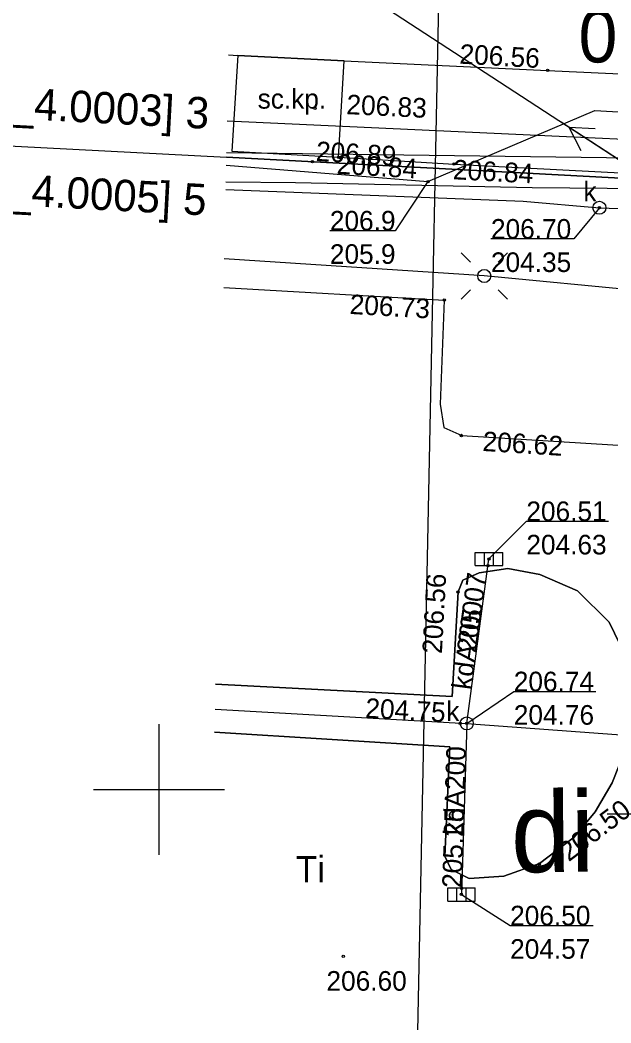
# Model space of a CAD drawing. Extents: x 6512606 to 6513006, y 6022524 to 6022728.
# Drawn here: x 6512694.69 to 6512717.27, y 6022641.08 to 6022679.43 of the extents above; entities that cross this region are included whole.
import ezdxf

# ---------------------------------------------------------------- set-up
doc = ezdxf.new("R2010")
doc.units = 0
for name, color, linetype in [('20', 7, 'Continuous'), ('208-opis obrębu', 7, 'Continuous'), ('210-oznaczenie konturu użytku gruntowego', 7, 'Continuous'), ('216-obręb ewidencyjny', 7, 'Continuous'), ('218-kontur użytku gruntowego', 7, 'Continuous'), ('219-działka ewidencyjna', 7, 'Continuous'), ('4', 7, 'Continuous'), ('chodnik (powierzchnia)', 7, 'Continuous'), ('Default', 7, 'Continuous'), ('jezdnia (powierzchnia)', 7, 'Continuous'), ('kratka ściekowa (punkt)', 7, 'Continuous'), ('krawężnik (linia)', 7, 'Continuous'), ('latarnia (punkt)', 7, 'Continuous'), ('maxp_inst_wodociągowa', 7, 'Continuous'), ('Obszar opracowania', 7, 'Continuous'), ('plac (powierzchnia)', 7, 'Continuous'), ('przewód elektroenergetyczny (linia)', 7, 'Continuous'), ('przewód elektroenergetyczny niskiego napięcia (linia)', 7, 'Continuous'), ('przewód elektroenergetyczny niskiego napięcia (linia) - symbol', 7, 'Continuous'), ('przewód kanalizacyjny (linia)', 7, 'Continuous'), ('przewód kanalizacyjny (linia)-Atr1', 7, 'Continuous'), ('przewód wodociągowy (linia)', 7, 'Continuous'), ('psr_os', 7, 'Continuous'), ('punkt o określonej wysokości (sieć elektroenergetyczna)', 7, 'Continuous'), ('punkt o określonej wysokości (sieć elektroenergetyczna)-Atr2', 7, 'Continuous'), ('punkt o określonej wysokości (sieć elektroenergetyczna)-Atr3', 7, 'Continuous'), ('punkt o określonej wysokości (sieć kanalizacyjna)', 7, 'Continuous'), ('punkt o określonej wysokości (sieć kanalizacyjna)-Atr2', 7, 'Continuous'), ('punkt o określonej wysokości (sieć kanalizacyjna)-Atr3', 7, 'Continuous'), ('punkt wysokościowy sztuczny', 7, 'Continuous'), ('punkt wysokościowy sztuczny-Atr2', 7, 'Continuous'), ('właz okrągły - siec kanalizacyjna (punkt)', 7, 'Continuous'), ('właz okrągły - siec kanalizacyjna (punkt)-Atr17', 7, 'Continuous'), ('ścieżka (powierzchnia)', 7, 'Continuous'), ('ścieżka (powierzchnia)-Atr17', 7, 'Continuous')]:
    doc.layers.add(name, color=color, linetype=linetype)

# ---------------------------------------------------------------- blocks, each defined once
blk = doc.blocks.new('PE04')
at = {"layer": 'Default'}
for p, q in [((46.5, 0), (37.84, 5)), ((6.5, 0), (0, 0)), ((6.5, 0), (16.5, 0)), ((16.5, 0), (26.5, 0)), ((26.5, 0), (36.5, 0)), ((36.5, 0), (46.5, 0)), ((46.5, 0), (37.84, -5)), ((46.5, 0), (50, 0))]:
    blk.add_line(p, q, dxfattribs=at)
blk = doc.blocks.new('PW01')
at = {"layer": 'Default'}
blk.add_circle((0, 0), 0.45, dxfattribs=at)
blk = doc.blocks.new('PW02')
at = {"layer": 'Default'}
blk.add_circle((0, 0), 0.45, dxfattribs=at)
blk = doc.blocks.new('US05')
at = {"layer": 'Default'}
for p, q in [((-5.25, -2.5), (-5.25, 2.5)), ((-5.25, 2.5), (-1.75, 2.5)), ((-1.75, -2.5), (-1.75, 2.5)), ((-1.75, 2.5), (1.75, 2.5)), ((1.75, -2.5), (1.75, 2.5)), ((1.75, 2.5), (5.25, 2.5)), ((5.25, -2.5), (5.25, 2.5)), ((-5.25, -2.5), (-1.75, -2.5)), ((-1.75, -2.5), (1.75, -2.5)), ((1.75, -2.5), (5.25, -2.5))]:
    blk.add_line(p, q, dxfattribs=at)
blk = doc.blocks.new('US22')
at = {"layer": 'Default'}
blk.add_circle((0, 0), 2.5, dxfattribs=at)
blk = doc.blocks.new('SM01')
at = {"layer": 'Default'}
for p, q in [((-5.3, 5.31), (-8.83, 8.84)), ((5.31, 5.31), (8.84, 8.84)), ((-5.3, -5.3), (-8.83, -8.83)), ((5.31, -5.3), (8.84, -8.83))]:
    blk.add_line(p, q, dxfattribs=at)
blk.add_circle((0, 0), 2.5, dxfattribs=at)

msp = doc.modelspace()

# ---------------------------------------------------------------- linework, layer by layer
at = {"layer": '20'}
msp.add_line((6512722.691, 6022649.066), (6512717.122, 6022649.066), dxfattribs=at)
at = {"layer": '216-obręb ewidencyjny'}
for points in [[(6512688.62, 6022674.91), (6512702.58, 6022674.18), (6512725.78, 6022672.95), (6512730.35, 6022672.71), (6512735.76, 6022672.94), (6512745.51, 6022673.33), (6512754.87, 6022673.72), (6512768.24, 6022674.27), (6512785.56, 6022674.74), (6512790.49, 6022674.74), (6512796.96, 6022674.74), (6512801.96, 6022670.34), (6512828.67, 6022670.98), (6512833.61, 6022675.02), (6512836.69, 6022675.17), (6512851.94, 6022675.93)], [(6512852.25, 6022608.25), (6512838.47, 6022634.29), (6512825.37, 6022649.66), (6512810.18, 6022663.28), (6512801.96, 6022670.34), (6512796.96, 6022674.74), (6512790.49, 6022674.74), (6512785.56, 6022674.74), (6512768.24, 6022674.27), (6512754.87, 6022673.72), (6512745.51, 6022673.33), (6512735.76, 6022672.94), (6512730.35, 6022672.71), (6512725.78, 6022672.95), (6512702.575, 6022674.177)]]:
    msp.add_lwpolyline(points, dxfattribs=at)
at = {"layer": '218-kontur użytku gruntowego'}
for points in [[(6512725.78, 6022672.95), (6512702.575, 6022674.178)], [(6512702.575, 6022674.178), (6512725.78, 6022672.95)]]:
    msp.add_lwpolyline(points, dxfattribs=at)
at = {"layer": '219-działka ewidencyjna'}
msp.add_lwpolyline([(6512702.575, 6022674.177), (6512725.78, 6022672.95)], dxfattribs=at)
at = {"layer": '4'}
msp.add_lwpolyline([(6512702.575, 6022674.177), (6512725.78, 6022672.95)], dxfattribs=at)
at = {"layer": 'chodnik (powierzchnia)'}
msp.add_lwpolyline([(6512706.86, 6022674.18), (6512711.28, 6022673.92), (6512732.54, 6022672.81)], dxfattribs=at)
at = {"layer": 'Default'}
for p, q in [((6512700, 6022647.5), (6512700, 6022652.5)), ((6512697.5, 6022650), (6512702.5, 6022650))]:
    msp.add_line(p, q, dxfattribs=at)
at = {"layer": 'jezdnia (powierzchnia)'}
msp.add_lwpolyline([(6512707.08, 6022677.87), (6512714.85, 6022677.5), (6512727.62, 6022676.91), (6512733.49, 6022676.74), (6512737.49, 6022676.65), (6512740.34, 6022676.65), (6512746.78, 6022676.72), (6512757.48, 6022676.77)], dxfattribs=at)
at = {"layer": 'krawężnik (linia)'}
for points in [[(6512702.655, 6022678.093), (6512703.01, 6022678.07), (6512707.08, 6022677.87)], [(6512707.08, 6022677.87), (6512714.85, 6022677.5), (6512727.62, 6022676.91), (6512733.49, 6022676.74), (6512737.49, 6022676.65), (6512740.34, 6022676.65), (6512746.78, 6022676.72), (6512757.48, 6022676.77)], [(6512702.473, 6022669.202), (6512710.9, 6022668.72), (6512710.75, 6022664.74), (6512710.88, 6022663.85), (6512711.57, 6022663.54), (6512725.79, 6022662.66), (6512724.94, 6022645.24), (6512724.45, 6022635.71), (6512706.43, 6022636.73), (6512701.814, 6022636.999)], [(6512711.21, 6022653.56), (6512711.43, 6022657.56), (6512711.61, 6022658.01), (6512712.23, 6022658.29), (6512713.33, 6022658.45), (6512714.55, 6022658.23), (6512715.99, 6022657.6), (6512717.2, 6022656.4), (6512718.01, 6022654.75), (6512718.25, 6022653.19), (6512717.88, 6022651.68), (6512717.32, 6022650.26), (6512716.67, 6022649.15), (6512715.87, 6022648.18), (6512714.54, 6022647.17), (6512713.18, 6022646.69), (6512711.85, 6022646.6), (6512711.17, 6022646.95), (6512710.93, 6022647.46), (6512711.12, 6022651.64), (6512702.125, 6022652.199)], [(6512702.163, 6022654.037), (6512711.21, 6022653.56)]]:
    msp.add_lwpolyline(points, dxfattribs=at)
at = {"layer": 'Obszar opracowania'}
msp.add_lwpolyline([(6512710.98, 6022693.84), (6512748.35, 6022694.16), (6512798.11, 6022695.25), (6512807.47, 6022695.46), (6512809.66, 6022606.87), (6512863.71, 6022622.03), (6512875.13, 6022581.36), (6512755.22, 6022535.25), (6512691.61, 6022568.03), (6512709.16, 6022605.16)], close=True, dxfattribs=at)
at = {"layer": 'plac (powierzchnia)'}
for points in [[(6512702.125, 6022652.199), (6512711.12, 6022651.64), (6512710.93, 6022647.46), (6512711.17, 6022646.95), (6512711.85, 6022646.6), (6512713.18, 6022646.69), (6512714.54, 6022647.17), (6512715.87, 6022648.18), (6512716.67, 6022649.15), (6512717.32, 6022650.26), (6512717.88, 6022651.68), (6512718.25, 6022653.19), (6512718.01, 6022654.75), (6512717.2, 6022656.4), (6512715.99, 6022657.6), (6512714.55, 6022658.23), (6512713.33, 6022658.45), (6512712.23, 6022658.29), (6512711.61, 6022658.01), (6512711.43, 6022657.56), (6512711.21, 6022653.56)], [(6512711.21, 6022653.56), (6512702.163, 6022654.037)]]:
    msp.add_lwpolyline(points, dxfattribs=at)
at = {"layer": 'przewód elektroenergetyczny (linia)'}
for points in [[(6512702.569, 6022673.878), (6512710.28, 6022673.25), (6512716.66, 6022675.97), (6512746.13, 6022674.3), (6512752.79, 6022674.32), (6512760.61, 6022675.35), (6512763.38, 6022676.06), (6512798.79, 6022676.04), (6512803.06, 6022673.02), (6512807.84, 6022668.96), (6512815.24, 6022662.53), (6512819.98, 6022657.77), (6512831.6, 6022645.79), (6512834.59, 6022642.25), (6512837.06, 6022638.75), (6512840.02, 6022634.13), (6512842.26, 6022630.04), (6512846.03, 6022621.35), (6512846.58, 6022618.9), (6512847.6, 6022616.23), (6512852.12, 6022605.09)], [(6512702.603, 6022675.567), (6512731.84, 6022674.22), (6512765.79, 6022675.22), (6512787.87, 6022675.5)], [(6512702.556, 6022673.235), (6512705.22, 6022673.21), (6512714.26, 6022673.02), (6512718.57, 6022672.98), (6512719.56, 6022672.79)], [(6512701.756, 6022634.173), (6512720.37, 6022633.07), (6512728.65, 6022632.8), (6512729.84, 6022646.1), (6512731.03, 6022668.44), (6512718.53, 6022669.06), (6512712.43, 6022669.64), (6512702.495, 6022670.296)]]:
    msp.add_lwpolyline(points, dxfattribs=at)
at = {"layer": 'przewód elektroenergetyczny niskiego napięcia (linia)'}
msp.add_lwpolyline([(6512702.771, 6022683.755), (6512719.56, 6022672.79)], dxfattribs=at)
at = {"layer": 'przewód kanalizacyjny (linia)'}
for points in [[(6512702.55, 6022672.944), (6512713.92, 6022672.5), (6512716.83, 6022672.25)], [(6512716.83, 6022672.25), (6512720.83, 6022672.11), (6512730.47, 6022671.7), (6512737.04, 6022671.58), (6512738.87, 6022671.48), (6512744.52, 6022671.09), (6512750.15, 6022670.75), (6512752.63, 6022670.67), (6512753.2, 6022670.48)], [(6512711.76, 6022652.53), (6512712.61, 6022658.82)], [(6512702.143, 6022653.075), (6512711.76, 6022652.53), (6512726.49, 6022651.44)], [(6512711.76, 6022652.53), (6512711.56, 6022645.99)]]:
    msp.add_lwpolyline(points, dxfattribs=at)
at = {"layer": 'przewód wodociągowy (linia)'}
msp.add_lwpolyline([(6512702.579, 6022674.359), (6512731.63, 6022673.98), (6512765.81, 6022675.09), (6512780.05, 6022675.09), (6512787.64, 6022675.26)], dxfattribs=at)
at = {"layer": 'punkt o określonej wysokości (sieć elektroenergetyczna)-Atr2'}
msp.add_lwpolyline([(6512710.28, 6022673.25), (6512709.03, 6022671.37), (6512706.53, 6022671.37)], dxfattribs=at)
at = {"layer": 'punkt o określonej wysokości (sieć kanalizacyjna)-Atr2'}
for points in [[(6512716.83, 6022672.25), (6512715.86, 6022671.06), (6512712.687, 6022671.06)], [(6512712.61, 6022658.82), (6512714.04, 6022660.26), (6512717.181, 6022660.26)], [(6512711.76, 6022652.53), (6512713.56, 6022653.75), (6512716.701, 6022653.75)], [(6512711.56, 6022645.99), (6512713.42, 6022644.8), (6512716.598, 6022644.8)]]:
    msp.add_lwpolyline(points, dxfattribs=at)
at = {"layer": 'ścieżka (powierzchnia)'}
msp.add_lwpolyline([(6512702.78, 6022674.41), (6512706.86, 6022674.18), (6512707.08, 6022677.87), (6512703.01, 6022678.07)], close=True, dxfattribs=at)

# ---------------------------------------------------------------- block references
at = {"layer": 'kratka ściekowa (punkt)', "xscale": 0.1, "yscale": 0.10000000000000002}
for p in [(6512712.61, 6022658.82), (6512711.56, 6022645.99)]:
    msp.add_blockref('US05', p, dxfattribs=at)
at = {"layer": 'latarnia (punkt)', "xscale": 0.1, "yscale": 0.10000000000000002}
msp.add_blockref('SM01', (6512712.43, 6022669.64), dxfattribs=at)
at = {"layer": 'przewód elektroenergetyczny niskiego napięcia (linia) - symbol', "xscale": 0.10000000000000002, "yscale": 0.1, "rotation": 146.851}
msp.add_blockref('PE04', (6512719.56, 6022672.79), dxfattribs=at)
at = {"layer": 'punkt o określonej wysokości (sieć elektroenergetyczna)', "xscale": 0.1, "yscale": 0.10000000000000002}
msp.add_blockref('PW01', (6512710.28, 6022673.25), dxfattribs=at)
at = {"layer": 'punkt o określonej wysokości (sieć kanalizacyjna)', "xscale": 0.1, "yscale": 0.10000000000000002}
for p in [(6512716.83, 6022672.25), (6512712.57, 6022658.56), (6512712.61, 6022658.82), (6512711.51, 6022652.54), (6512711.76, 6022652.53), (6512711.56, 6022645.99), (6512711.57, 6022646.23)]:
    msp.add_blockref('PW01', p, dxfattribs=at)
at = {"layer": 'punkt wysokościowy sztuczny', "xscale": 0.1, "yscale": 0.10000000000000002}
for p in [(6512714.85, 6022677.5), (6512705.96, 6022676.05), (6512705.86, 6022674.01), (6512706.86, 6022674.18), (6512711.28, 6022673.92), (6512710.9, 6022668.72), (6512711.56, 6022663.54), (6512711.43, 6022657.56), (6512714.54, 6022647.16), (6512707.04, 6022643.63)]:
    msp.add_blockref('PW02', p, dxfattribs=at)
at = {"layer": 'właz okrągły - siec kanalizacyjna (punkt)', "xscale": 0.1, "yscale": 0.10000000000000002}
for p in [(6512716.83, 6022672.25), (6512711.76, 6022652.53)]:
    msp.add_blockref('US22', p, dxfattribs=at)

# ---------------------------------------------------------------- texts
at = {"layer": '208-opis obrębu'}
for s, p in [('[220502_4.0003] 3', (6512688.52, 6022675.97)), ('[220502_4.0005] 5', (6512688.42, 6022672.66))]:
    msp.add_text(s, height=1.2, rotation=356.973, dxfattribs=at).set_placement(p)
at = {"layer": '210-oznaczenie konturu użytku gruntowego'}
msp.add_text('Ti', height=1, dxfattribs=at).set_placement((6512705.23, 6022646.46))
at = {"layer": 'maxp_inst_wodociągowa'}
msp.add_text('di', height=3.0671, rotation=0.5777, dxfattribs=at).set_placement((6512713.462, 6022646.832))
at = {"layer": 'przewód kanalizacyjny (linia)-Atr1'}
for rotation, p in [(82.304, (6512711.93, 6022653.79)), (88.248, (6512711.63, 6022648.25))]:
    msp.add_text('kdA200', height=0.75, rotation=rotation, dxfattribs=at).set_placement(p)
at = {"layer": 'psr_os'}
msp.add_text('0+000.00', height=2, rotation=359.5356, dxfattribs=at).set_placement((6512716.024, 6022677.811))
at = {"layer": 'punkt o określonej wysokości (sieć elektroenergetyczna)-Atr2'}
msp.add_text('206.9', height=0.75, dxfattribs=at).set_placement((6512706.53, 6022671.378))
at = {"layer": 'punkt o określonej wysokości (sieć elektroenergetyczna)-Atr3'}
msp.add_text('205.9', height=0.75, dxfattribs=at).set_placement((6512706.53, 6022670.103))
at = {"layer": 'punkt o określonej wysokości (sieć kanalizacyjna)-Atr2'}
for s, p in [('206.70', (6512712.687, 6022671.067)), ('206.51', (6512714.04, 6022660.268)), ('206.74', (6512713.56, 6022653.758)), ('206.50', (6512713.42, 6022644.808))]:
    msp.add_text(s, height=0.75, dxfattribs=at).set_placement(p)
at = {"layer": 'punkt o określonej wysokości (sieć kanalizacyjna)-Atr3'}
for s, p in [('204.35', (6512712.687, 6022669.792)), ('204.63', (6512714.04, 6022658.992)), ('204.76', (6512713.56, 6022652.482)), ('204.57', (6512713.42, 6022643.532))]:
    msp.add_text(s, height=0.75, dxfattribs=at).set_placement(p)
for s, rotation, p in [('205.07', 82.304, (6512712.12, 6022655.2)), ('204.75', 356.757, (6512707.87, 6022652.75)), ('205.25', 88.248, (6512711.57, 6022646.23))]:
    msp.add_text(s, height=0.75, rotation=rotation, dxfattribs=at).set_placement(p)
at = {"layer": 'punkt wysokościowy sztuczny-Atr2'}
for s, rotation, p in [('206.56', 356.828, (6512711.47, 6022677.76)), ('206.83', 357.274, (6512707.15, 6022675.83)), ('206.89', 356.516, (6512705.98, 6022674.04)), ('206.84', 356.633, (6512706.78, 6022673.55)), ('206.84', 357.011, (6512711.22, 6022673.34)), ('206.73', 356.724, (6512707.27, 6022668.19)), ('206.62', 356.458, (6512712.35, 6022662.95)), ('206.56', 86.852, (6512710.81, 6022655.18)), ('206.50', 37.212, (6512715.66, 6022647.22))]:
    msp.add_text(s, height=0.75, rotation=rotation, dxfattribs=at).set_placement(p)
msp.add_text('206.60', height=0.75, dxfattribs=at).set_placement((6512706.4, 6022642.31))
at = {"layer": 'właz okrągły - siec kanalizacyjna (punkt)-Atr17'}
for p in [(6512716.22, 6022672.49), (6512710.98, 6022652.62)]:
    msp.add_text('k', height=0.75, dxfattribs=at).set_placement(p)
at = {"layer": 'ścieżka (powierzchnia)-Atr17'}
msp.add_text('sc.kp.', height=0.75, dxfattribs=at).set_placement((6512703.77, 6022676.04))

doc.saveas('drawing.dxf')
